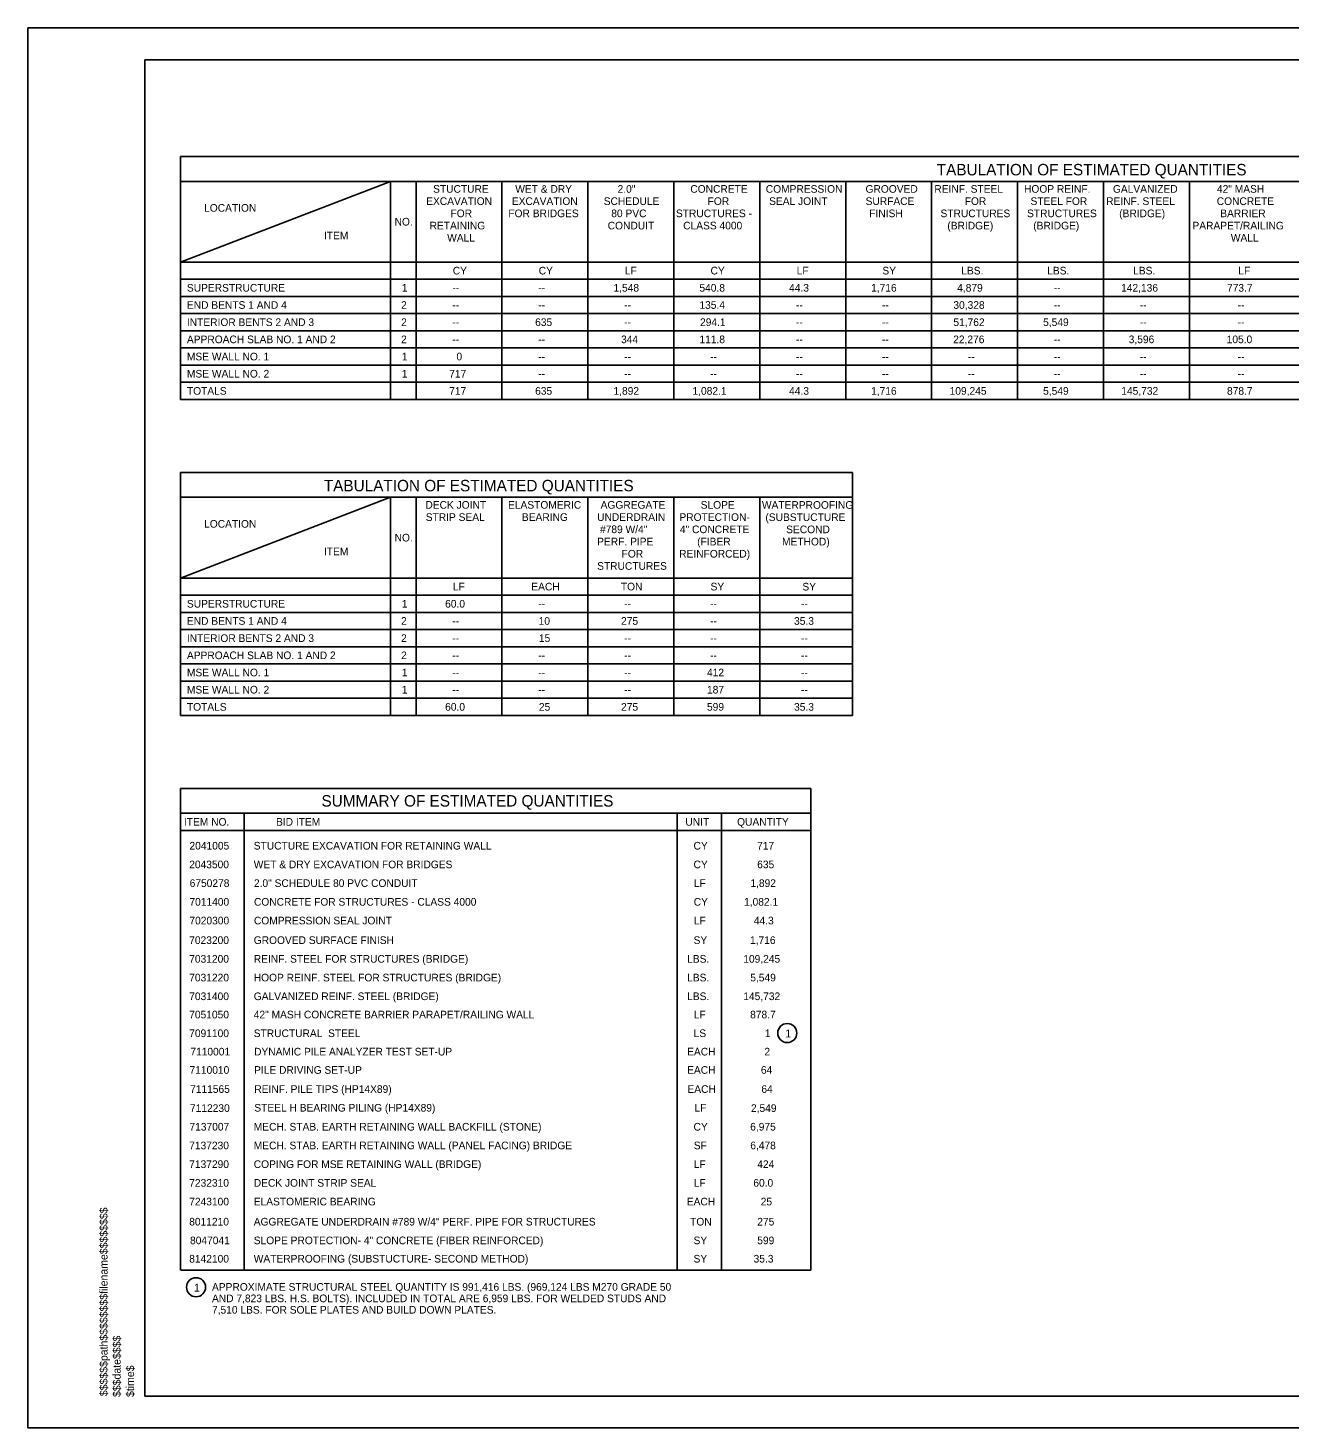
# Model space of a CAD drawing. Extents: x -125.5 to -89.4, y -5.1 to 16.9.
# Drawn here: x -125.53 to -105.71, y -5.07 to 16.93 of the extents above; entities that cross this region are included whole.
import ezdxf

# ---------------------------------------------------------------- set-up
doc = ezdxf.new("R2010")
doc.units = 0
for name, color, linetype in [('BR_BORDER LINES', 7, 'Continuous'), ('BR_TABLE LINES', 7, 'Continuous'), ('BR_TEXT', 7, 'Continuous'), ('Level 31', 7, 'Continuous'), ('RD_SHT_ID', 7, 'Continuous')]:
    doc.layers.add(name, color=color, linetype=linetype)

msp = doc.modelspace()

# ---------------------------------------------------------------- linework, layer by layer
at = {"layer": 'BR_BORDER LINES'}
for p, q in [((-90.033, 16.434), (-123.699, 16.434)), ((-123.699, -4.566), (-123.699, 16.434)), ((-123.699, -4.566), (-90.033, -4.566))]:
    msp.add_line(p, q, dxfattribs=at)
at = {"layer": 'BR_TABLE LINES'}
for p, q in [((-123.136, 14.914), (-94.796, 14.914)), ((-123.136, 14.914), (-123.136, 11.096)), ((-123.136, 14.524), (-94.796, 14.524)), ((-123.136, 13.256), (-119.836, 14.524)), ((-119.836, 14.524), (-119.836, 11.096)), ((-119.436, 14.524), (-119.436, 11.096)), ((-118.086, 14.524), (-118.086, 11.096)), ((-116.736, 14.524), (-116.736, 11.096)), ((-115.386, 14.524), (-115.386, 11.096)), ((-114.036, 14.524), (-114.036, 11.096)), ((-112.686, 14.524), (-112.686, 11.096)), ((-111.336, 14.524), (-111.336, 11.096)), ((-109.986, 14.524), (-109.986, 11.096)), ((-108.636, 14.524), (-108.636, 11.096)), ((-107.286, 14.524), (-107.286, 11.096)), ((-123.136, 13.256), (-94.796, 13.256)), ((-123.136, 12.986), (-94.796, 12.986)), ((-94.796, 12.716), (-123.136, 12.716)), ((-94.796, 12.446), (-123.136, 12.446)), ((-94.796, 12.176), (-123.136, 12.176)), ((-94.796, 11.906), (-123.136, 11.906)), ((-94.796, 11.636), (-123.136, 11.636)), ((-94.796, 11.366), (-123.136, 11.366)), ((-94.796, 11.096), (-123.136, 11.096)), ((-123.136, 9.949), (-123.136, 6.131)), ((-112.58, 9.949), (-123.136, 9.949)), ((-123.136, 9.949), (-112.58, 9.949)), ((-112.58, 9.949), (-112.58, 6.131)), ((-123.136, 9.559), (-112.58, 9.559)), ((-123.136, 8.291), (-119.836, 9.559)), ((-119.836, 9.559), (-119.836, 6.131)), ((-119.436, 9.559), (-119.436, 6.131)), ((-118.086, 9.559), (-118.086, 6.131)), ((-116.736, 9.559), (-116.736, 6.131)), ((-115.386, 9.559), (-115.386, 6.131)), ((-114.036, 9.558), (-114.036, 6.131)), ((-123.136, 8.291), (-112.58, 8.291)), ((-123.136, 8.021), (-112.58, 8.021)), ((-112.58, 7.751), (-123.136, 7.751)), ((-112.58, 7.481), (-123.136, 7.481)), ((-112.58, 7.211), (-123.136, 7.211)), ((-112.58, 6.941), (-123.136, 6.941)), ((-112.58, 6.671), (-123.136, 6.671)), ((-112.58, 6.401), (-123.136, 6.401)), ((-112.58, 6.131), (-123.136, 6.131)), ((-123.136, -2.586), (-123.136, 4.984)), ((-123.136, 4.984), (-113.236, 4.984)), ((-113.236, -2.586), (-113.236, 4.984)), ((-123.136, 4.594), (-113.236, 4.594)), ((-122.136, -2.586), (-122.136, 4.594)), ((-115.336, -2.586), (-115.336, 4.594)), ((-114.636, -2.586), (-114.636, 4.594)), ((-123.136, 4.324), (-113.236, 4.324)), ((-123.131, -2.586), (-113.231, -2.586))]:
    msp.add_line(p, q, dxfattribs=at)
at = {"layer": 'BR_TEXT'}
for centre in [(-113.604, 1.14), (-122.893, -2.854)]:
    msp.add_circle(centre, 0.15, dxfattribs=at)
at = {"layer": 'Level 31'}
msp.add_line((-89.533, 16.934), (-125.533, 16.934), dxfattribs=at)
msp.add_lwpolyline([(-125.533, 16.934), (-125.533, -5.066), (-89.533, -5.066), (-89.533, 16.934)], dxfattribs=at)

# ---------------------------------------------------------------- texts
at = {"layer": 'BR_TEXT'}
for s, height, p in [('TABULATION OF ESTIMATED QUANTITIES', 0.18, (-111.255, 14.618)), ('STUCTURE ', 0.12, (-119.168, 14.345)), ('WET & DRY', 0.12, (-117.877, 14.345)), ('2.0"', 0.12, (-116.27, 14.345)), ('CONCRETE ', 0.12, (-115.127, 14.345)), ('COMPRESSION', 0.12, (-113.941, 14.345)), ('GROOVED ', 0.12, (-112.374, 14.345)), ('REINF. STEEL', 0.12, (-111.293, 14.345)), ('HOOP REINF. ', 0.12, (-109.884, 14.345)), ('GALVANIZED ', 0.12, (-108.487, 14.345)), ('42" MASH ', 0.12, (-106.853, 14.345)), ('LOCATION', 0.12, (-122.766, 14.047)), ('EXCAVATION ', 0.12, (-119.277, 14.153)), ('FOR ', 0.12, (-118.895, 13.961)), ('FOR BRIDGES', 0.12, (-117.986, 13.961)), ('EXCAVATION', 0.12, (-117.931, 14.153)), (' SCHEDULE', 0.12, (-116.532, 14.153)), ('80 PVC ', 0.12, (-116.369, 13.961)), ('STRUCTURES - ', 0.12, (-115.353, 13.961)), ('FOR ', 0.12, (-114.855, 14.153)), ('SEAL JOINT', 0.12, (-113.889, 14.153)), ('SURFACE ', 0.12, (-112.373, 14.153)), ('FINISH', 0.12, (-112.316, 13.961)), (' STRUCTURES ', 0.12, (-111.241, 13.961)), (' FOR', 0.12, (-110.86, 14.153)), ('STRUCTURES ', 0.12, (-109.837, 13.961)), ('STEEL FOR ', 0.12, (-109.782, 14.153)), ('REINF. STEEL ', 0.12, (-108.593, 14.153)), ('(BRIDGE)', 0.12, (-108.389, 13.961)), ('CONCRETE ', 0.12, (-106.856, 14.153)), ('BARRIER ', 0.12, (-106.801, 13.961)), ('NO.', 0.12, (-119.773, 13.83)), ('RETAINING ', 0.12, (-119.223, 13.769)), ('CONDUIT', 0.12, (-116.425, 13.769)), ('CLASS 4000', 0.12, (-115.239, 13.769)), ('(BRIDGE)', 0.12, (-111.089, 13.769)), ('(BRIDGE)', 0.12, (-109.739, 13.769)), ('PARAPET/RAILING ', 0.12, (-107.238, 13.769)), ('ITEM', 0.12, (-120.883, 13.613)), ('WALL', 0.12, (-118.947, 13.577)), ('WALL', 0.12, (-106.635, 13.577)), ('CY', 0.12, (-118.859, 13.061)), ('CY', 0.12, (-117.509, 13.061)), ('LF', 0.12, (-116.156, 13.061)), ('CY', 0.12, (-114.809, 13.061)), ('LF', 0.12, (-113.456, 13.061)), ('SY', 0.12, (-112.109, 13.061)), ('LBS.', 0.12, (-110.87, 13.061)), ('LBS.', 0.12, (-109.52, 13.061)), ('LBS.', 0.12, (-108.17, 13.061)), ('LF', 0.12, (-106.517, 13.061)), ('SUPERSTRUCTURE', 0.12, (-123.036, 12.791)), ('1', 0.12, (-119.661, 12.791)), ('--', 0.12, (-118.864, 12.791)), ('--', 0.12, (-117.516, 12.791)), ('1,548', 0.12, (-116.334, 12.791)), ('540.8', 0.12, (-114.984, 12.791)), ('44.3', 0.12, (-113.575, 12.791)), ('1,716', 0.12, (-112.287, 12.791)), ('4,879', 0.12, (-110.934, 12.791)), ('--', 0.12, (-109.416, 12.791)), ('142,136', 0.12, (-108.359, 12.791)), ('773.7', 0.12, (-106.695, 12.791)), ('END BENTS 1 AND 4', 0.12, (-123.036, 12.521)), ('2', 0.12, (-119.671, 12.521)), ('--', 0.12, (-118.866, 12.521)), ('--', 0.12, (-117.516, 12.521)), ('--', 0.12, (-116.166, 12.521)), ('135.4', 0.12, (-114.984, 12.521)), ('--', 0.12, (-113.466, 12.521)), ('--', 0.12, (-112.116, 12.521)), ('30,328', 0.12, (-110.994, 12.521)), ('--', 0.12, (-109.416, 12.521)), ('--', 0.12, (-108.066, 12.521)), ('--', 0.12, (-106.527, 12.521)), ('INTERIOR BENTS 2 AND 3', 0.12, (-123.036, 12.251)), ('2', 0.12, (-119.671, 12.251)), ('635', 0.12, (-117.565, 12.251)), ('294.1', 0.12, (-114.974, 12.251)), ('51,762', 0.12, (-110.994, 12.251)), ('5,549', 0.12, (-109.584, 12.251)), ('APPROACH SLAB NO. 1 AND 2', 0.12, (-123.036, 11.981)), ('2', 0.12, (-119.671, 11.981)), ('--', 0.12, (-118.866, 12.251)), ('344', 0.12, (-116.215, 11.981)), ('--', 0.12, (-116.166, 12.251)), ('111.8', 0.12, (-114.984, 11.981)), ('--', 0.12, (-113.466, 12.251)), ('--', 0.12, (-112.116, 12.251)), ('22,276', 0.12, (-110.997, 11.981)), ('3,596', 0.12, (-108.239, 11.981)), ('--', 0.12, (-108.066, 12.251)), ('105.0', 0.12, (-106.7, 11.981)), ('--', 0.12, (-106.527, 12.251)), ('--', 0.12, (-118.866, 11.981)), ('--', 0.12, (-117.516, 11.981)), ('--', 0.12, (-113.466, 11.981)), ('--', 0.12, (-112.116, 11.981)), ('--', 0.12, (-109.416, 11.981)), ('MSE WALL NO. 1', 0.12, (-123.036, 11.711)), ('1', 0.12, (-119.661, 11.711)), ('0', 0.12, (-118.801, 11.711)), ('--', 0.12, (-117.516, 11.711)), ('--', 0.12, (-116.166, 11.711)), ('--', 0.12, (-114.816, 11.711)), ('--', 0.12, (-113.466, 11.711)), ('--', 0.12, (-112.116, 11.711)), ('--', 0.12, (-110.766, 11.711)), ('--', 0.12, (-109.416, 11.711)), ('--', 0.12, (-108.066, 11.711)), ('--', 0.12, (-106.527, 11.711)), ('MSE WALL NO. 2', 0.12, (-123.036, 11.441)), ('1', 0.12, (-119.661, 11.441)), ('717', 0.12, (-118.915, 11.441)), ('--', 0.12, (-117.516, 11.441)), ('--', 0.12, (-116.166, 11.441)), ('--', 0.12, (-114.816, 11.441)), ('--', 0.12, (-113.466, 11.441)), ('--', 0.12, (-112.116, 11.441)), ('--', 0.12, (-110.766, 11.441)), ('--', 0.12, (-109.416, 11.441)), ('--', 0.12, (-108.066, 11.441)), ('--', 0.12, (-106.527, 11.441)), ('TOTALS', 0.12, (-123.036, 11.171)), ('717', 0.12, (-118.915, 11.171)), ('635', 0.12, (-117.565, 11.171)), ('1,892', 0.12, (-116.334, 11.171)), ('1,082.1', 0.12, (-115.093, 11.171)), ('44.3', 0.12, (-113.575, 11.171)), ('1,716', 0.12, (-112.287, 11.171)), ('109,245', 0.12, (-111.053, 11.171)), ('5,549', 0.12, (-109.584, 11.171)), ('145,732', 0.12, (-108.356, 11.171)), ('878.7', 0.12, (-106.695, 11.171)), ('TABULATION OF ESTIMATED QUANTITIES', 0.18, (-120.885, 9.653)), ('DECK JOINT ', 0.12, (-119.289, 9.38)), ('ELASTOMERIC ', 0.12, (-117.991, 9.38)), ('AGGREGATE ', 0.12, (-116.536, 9.38)), ('SLOPE ', 0.12, (-114.964, 9.38)), ('WATERPROOFING ', 0.12, (-114.002, 9.379)), ('STRIP SEAL', 0.12, (-119.284, 9.188)), ('BEARING', 0.12, (-117.773, 9.188)), ('UNDERDRAIN ', 0.12, (-116.591, 9.188)), ('PROTECTION- ', 0.12, (-115.298, 9.188)), ('(SUBSTUCTURE', 0.12, (-113.947, 9.187)), ('LOCATION', 0.12, (-122.766, 9.082)), ('#789 W/4" ', 0.12, (-116.546, 8.996)), ('4" CONCRETE ', 0.12, (-115.291, 8.996)), ('SECOND ', 0.12, (-113.621, 8.995)), ('NO.', 0.12, (-119.773, 8.865)), ('PERF. PIPE ', 0.12, (-116.591, 8.804)), ('(FIBER ', 0.12, (-115.019, 8.804)), ('METHOD)', 0.12, (-113.686, 8.803)), ('ITEM', 0.12, (-120.883, 8.648)), ('FOR ', 0.12, (-116.206, 8.612)), ('REINFORCED)', 0.12, (-115.302, 8.612)), ('STRUCTURES', 0.12, (-116.591, 8.42)), ('LF', 0.12, (-118.856, 8.096)), ('EACH', 0.12, (-117.625, 8.096)), ('TON', 0.12, (-116.218, 8.096)), ('SY', 0.12, (-114.809, 8.096)), ('SY', 0.12, (-113.366, 8.095)), ('SUPERSTRUCTURE', 0.12, (-123.036, 7.826)), ('1', 0.12, (-119.661, 7.826)), ('1', 0.12, (-119.661, 7.826)), ('60.0', 0.12, (-118.979, 7.826)), ('--', 0.12, (-117.516, 7.826)), ('--', 0.12, (-116.166, 7.826)), ('--', 0.12, (-114.816, 7.826)), ('--', 0.12, (-113.388, 7.826)), ('END BENTS 1 AND 4', 0.12, (-123.036, 7.556)), ('2', 0.12, (-119.671, 7.556)), ('--', 0.12, (-118.866, 7.556)), ('10', 0.12, (-117.51, 7.556)), ('275', 0.12, (-116.215, 7.556)), ('--', 0.12, (-114.816, 7.556)), ('35.3', 0.12, (-113.497, 7.556)), ('INTERIOR BENTS 2 AND 3', 0.12, (-123.036, 7.286)), ('2', 0.12, (-119.671, 7.286)), ('--', 0.12, (-118.866, 7.286)), ('15', 0.12, (-117.506, 7.286)), ('--', 0.12, (-116.166, 7.286)), ('--', 0.12, (-114.816, 7.286)), ('--', 0.12, (-113.388, 7.286)), ('APPROACH SLAB NO. 1 AND 2', 0.12, (-123.036, 7.016)), ('2', 0.12, (-119.671, 7.016)), ('--', 0.12, (-118.866, 7.016)), ('--', 0.12, (-117.516, 7.016)), ('--', 0.12, (-116.166, 7.016)), ('--', 0.12, (-114.816, 7.016)), ('--', 0.12, (-113.388, 7.016)), ('MSE WALL NO. 1', 0.12, (-123.036, 6.746)), ('1', 0.12, (-119.661, 6.746)), ('412', 0.12, (-114.865, 6.746)), ('--', 0.12, (-118.866, 6.746)), ('--', 0.12, (-117.516, 6.746)), ('--', 0.12, (-116.166, 6.746)), ('--', 0.12, (-113.388, 6.746)), ('MSE WALL NO. 2', 0.12, (-123.036, 6.476)), ('1', 0.12, (-119.661, 6.476)), ('--', 0.12, (-118.866, 6.476)), ('--', 0.12, (-117.516, 6.476)), ('--', 0.12, (-116.166, 6.476)), ('187', 0.12, (-114.865, 6.476)), ('--', 0.12, (-113.388, 6.476)), ('TOTALS', 0.12, (-123.036, 6.206)), ('60.0', 0.12, (-118.979, 6.206)), ('25', 0.12, (-117.506, 6.206)), ('275', 0.12, (-116.215, 6.206)), ('599', 0.12, (-114.865, 6.206)), ('35.3', 0.12, (-113.497, 6.206)), ('SUMMARY OF ESTIMATED QUANTITIES', 0.18, (-120.922, 4.699)), ('ITEM NO.', 0.12, (-123.083, 4.399)), ('BID ITEM', 0.12, (-121.636, 4.399)), ('UNIT', 0.12, (-115.205, 4.399)), ('QUANTITY', 0.12, (-114.392, 4.399)), ('2041005', 0.12, (-122.996, 4.024)), ('STUCTURE EXCAVATION FOR RETAINING WALL', 0.12, (-121.986, 4.024)), ('CY', 0.12, (-115.076, 4.024)), ('717', 0.12, (-114.078, 4.024)), ('2043500', 0.12, (-123, 3.73)), ('WET & DRY EXCAVATION FOR BRIDGES', 0.12, (-121.986, 3.73)), ('CY', 0.12, (-115.076, 3.73)), ('635', 0.12, (-114.076, 3.73)), ('6750278', 0.12, (-122.993, 3.436)), ('2.0" SCHEDULE 80 PVC CONDUIT', 0.12, (-121.983, 3.436)), ('LF', 0.12, (-115.07, 3.436)), ('1,892', 0.12, (-114.183, 3.436)), ('7011400', 0.12, (-122.997, 3.142)), ('CONCRETE FOR STRUCTURES - CLASS 4000', 0.12, (-121.983, 3.142)), ('CY', 0.12, (-115.073, 3.142)), ('1,082.1', 0.12, (-114.283, 3.142)), ('7020300', 0.12, (-122.997, 2.848)), ('COMPRESSION SEAL JOINT', 0.12, (-121.983, 2.848)), ('LF', 0.12, (-115.07, 2.848)), ('44.3', 0.12, (-114.129, 2.848)), ('7023200', 0.12, (-123, 2.54)), ('GROOVED SURFACE FINISH', 0.12, (-121.986, 2.54)), ('SY', 0.12, (-115.076, 2.54)), ('1,716', 0.12, (-114.189, 2.54)), ('7031200', 0.12, (-123, 2.246)), ('REINF. STEEL FOR STRUCTURES (BRIDGE)', 0.12, (-121.986, 2.246)), ('LBS.', 0.12, (-115.177, 2.246)), ('109,245', 0.12, (-114.295, 2.246)), ('7031220', 0.12, (-123, 1.952)), ('HOOP REINF. STEEL FOR STRUCTURES (BRIDGE)', 0.12, (-121.986, 1.952)), ('LBS.', 0.12, (-115.177, 1.952)), ('5,549', 0.12, (-114.185, 1.952)), ('7031400', 0.12, (-123, 1.658)), ('GALVANIZED REINF. STEEL (BRIDGE)', 0.12, (-121.986, 1.658)), ('LBS.', 0.12, (-115.177, 1.658)), ('145,732', 0.12, (-114.295, 1.658)), ('7051050', 0.12, (-123, 1.371)), ('42" MASH CONCRETE BARRIER PARAPET/RAILING WALL', 0.12, (-121.986, 1.371)), ('LF', 0.12, (-115.073, 1.371)), ('878.7', 0.12, (-114.187, 1.371)), ('7091100', 0.12, (-123, 1.077)), ('STRUCTURAL  STEEL', 0.12, (-121.986, 1.077)), ('LS', 0.12, (-115.075, 1.077)), ('1', 0.12, (-113.956, 1.077)), ('7110001', 0.12, (-122.982, 0.788)), ('DYNAMIC PILE ANALYZER TEST SET-UP', 0.12, (-121.981, 0.788)), ('EACH', 0.12, (-115.177, 0.788)), ('2', 0.12, (-113.963, 0.788)), ('7110010', 0.12, (-122.995, 0.5)), ('PILE DRIVING SET-UP', 0.12, (-121.981, 0.5)), ('EACH', 0.12, (-115.177, 0.5)), ('64', 0.12, (-114.018, 0.5)), ('7111565', 0.12, (-122.986, 0.2)), ('REINF. PILE TIPS (HP14X89)', 0.12, (-121.977, 0.2)), ('EACH', 0.12, (-115.172, 0.2)), ('64', 0.12, (-114.011, 0.2)), ('7112230', 0.12, (-122.988, -0.099)), ('STEEL H BEARING PILING (HP14X89)', 0.12, (-121.977, -0.094)), ('LF', 0.12, (-115.063, -0.094)), ('2,549', 0.12, (-114.174, -0.099)), ('7137007', 0.12, (-122.996, -0.392)), ('MECH. STAB. EARTH RETAINING WALL BACKFILL (STONE)', 0.12, (-121.986, -0.392)), ('CY', 0.12, (-115.076, -0.392)), ('6,975', 0.12, (-114.186, -0.392)), ('7137230', 0.12, (-123, -0.686)), ('MECH. STAB. EARTH RETAINING WALL (PANEL FACING) BRIDGE', 0.12, (-121.986, -0.686)), ('SF', 0.12, (-115.073, -0.686)), ('6,478', 0.12, (-114.185, -0.686)), ('7137290', 0.12, (-123, -0.98)), ('COPING FOR MSE RETAINING WALL (BRIDGE)', 0.12, (-121.986, -0.98)), ('LF', 0.12, (-115.073, -0.98)), ('424', 0.12, (-114.075, -0.98)), ('7232310', 0.12, (-123, -1.274)), ('DECK JOINT STRIP SEAL', 0.12, (-121.986, -1.274)), ('LF', 0.12, (-115.073, -1.274)), ('60.0', 0.12, (-114.137, -1.274)), ('7243100', 0.12, (-123, -1.568)), ('ELASTOMERIC BEARING', 0.12, (-121.986, -1.568)), ('EACH', 0.12, (-115.182, -1.568)), ('25', 0.12, (-114.021, -1.568)), ('AGGREGATE UNDERDRAIN #789 W/4" PERF. PIPE FOR STRUCTURES', 0.12, (-121.986, -1.884)), ('8011210', 0.12, (-123, -1.884)), ('TON', 0.12, (-115.13, -1.884)), ('275', 0.12, (-114.075, -1.884)), ('8047041', 0.12, (-122.987, -2.178)), ('SLOPE PROTECTION- 4" CONCRETE (FIBER REINFORCED)', 0.12, (-121.986, -2.178)), ('SY', 0.12, (-115.076, -2.178)), ('599', 0.12, (-114.075, -2.178)), ('8142100', 0.12, (-123, -2.466)), ('WATERPROOFING (SUBSTUCTURE- SECOND METHOD)', 0.12, (-121.986, -2.466)), ('SY', 0.12, (-115.076, -2.466)), ('35.3', 0.12, (-114.133, -2.466)), ('APPROXIMATE STRUCTURAL STEEL QUANTITY IS 991,416 LBS. (969,124 LBS M270 GRADE 50', 0.12, (-122.642, -2.909)), ('AND 7,823 LBS. H.S. BOLTS). INCLUDED IN TOTAL ARE 6,959 LBS. FOR WELDED STUDS AND', 0.12, (-122.642, -3.089)), ('7,510 LBS. FOR SOLE PLATES AND BUILD DOWN PLATES.', 0.12, (-122.642, -3.269))]:
    msp.add_text(s, height=height, dxfattribs=at).set_placement(p)
for p in [(-113.635, 1.071), (-122.925, -2.923)]:
    msp.add_text('1', height=0.125, rotation=360, dxfattribs=at).set_placement(p)
at = {"layer": 'RD_SHT_ID'}
for s, height, p in [('$$$$$$path$$$$$$$$filename$$$$$$$$', 0.12347, (-124.283, -4.566)), ('$$$date$$$$', 0.12347, (-124.077, -4.579)), ('$time$', 0.1235, (-123.866, -4.579))]:
    msp.add_text(s, height=height, rotation=90, dxfattribs=at).set_placement(p)

doc.saveas('drawing.dxf')
